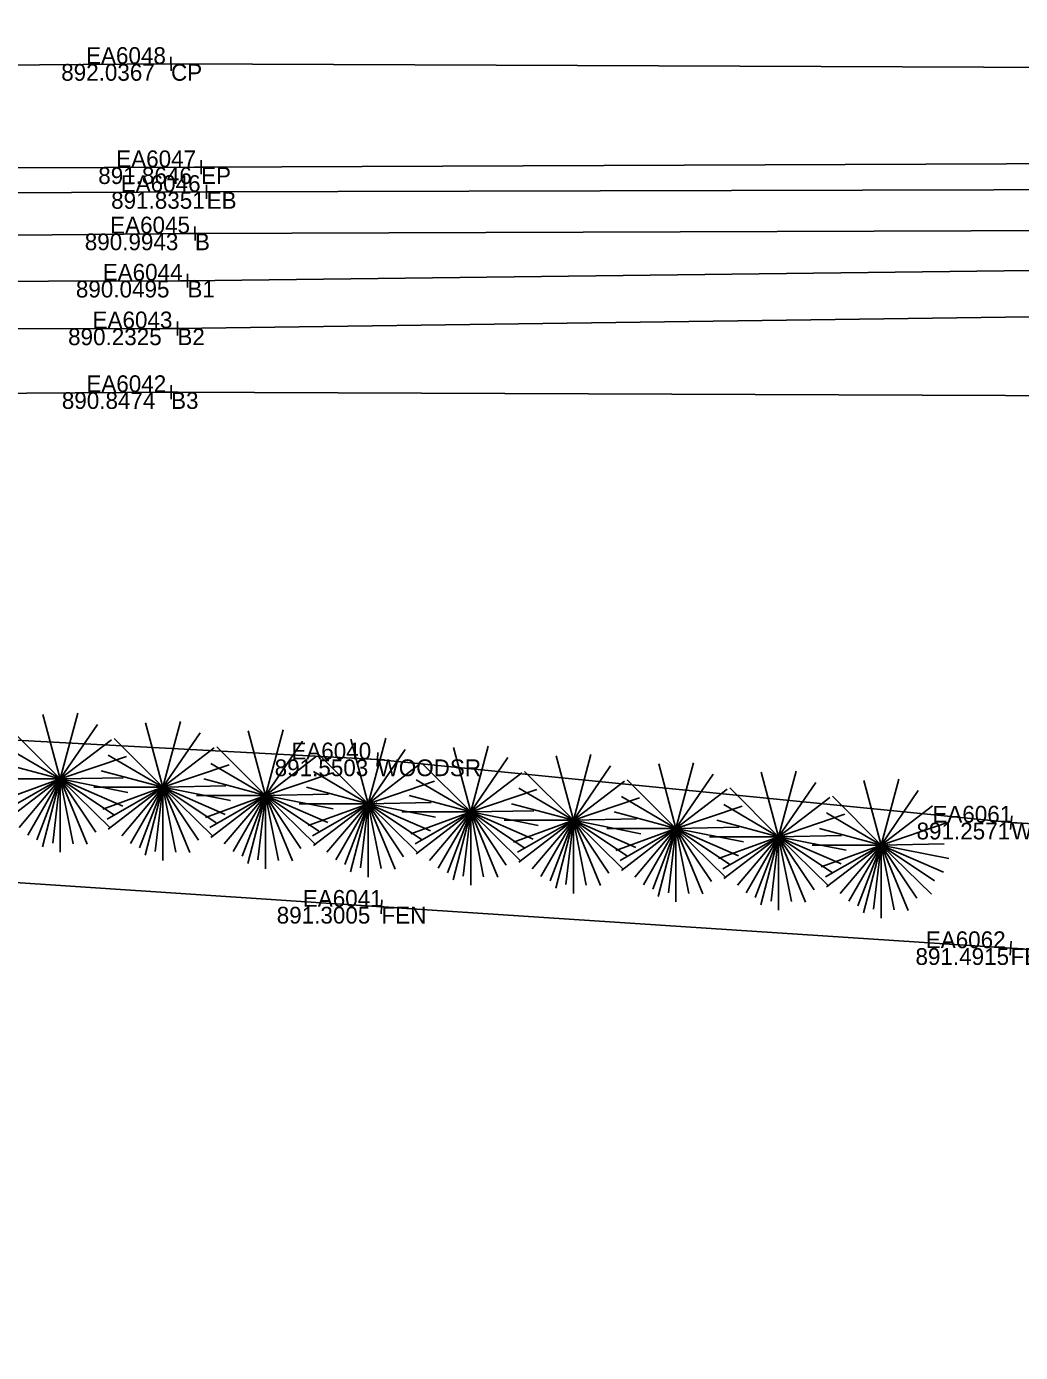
# Model space of a CAD drawing. Extents: x 179044 to 189691, y 286531 to 301257.
# Drawn here: x 179870.8 to 179941.9, y 300496.5 to 300591.3 of the extents above; entities that cross this region are included whole.
import ezdxf

# ---------------------------------------------------------------- set-up
doc = ezdxf.new("R2010")
doc.units = 0
for name, color, linetype in [('PV_X_COP', 7, 'Continuous'), ('PV_X_EOP', 7, 'Continuous'), ('PV_X_Shoulder_Aggregate', 7, 'Continuous'), ('RD_X_Fence', 7, 'Continuous'), ('SV_X_Break_Lines', 7, 'Continuous'), ('SV_X_Shot_Marker', 7, 'Continuous'), ('SV_X_Text_Comment', 7, 'Continuous'), ('SV_X_Text_Elevation', 7, 'Continuous'), ('SV_X_Text_Name', 7, 'Continuous'), ('VG_X_Cells', 7, 'Continuous'), ('VG_X_Text', 7, 'Continuous'), ('VG_X_Tree_Line_Lt', 7, 'Continuous')]:
    doc.layers.add(name, color=color, linetype=linetype)

msp = doc.modelspace()

# ---------------------------------------------------------------- linework, layer by layer
at = {"layer": 'PV_X_COP'}
msp.add_lwpolyline([(179370.611, 300584.893), (179476.831, 300585.936), (179562.951, 300586.92), (179659.852, 300587.603), (179771.173, 300587.773), (179881.154, 300588.595), (179985.728, 300588.166), (180079.826, 300588.612), (180147.691, 300589.874), (180172.034, 300590.636), (180187.456, 300591.905), (180203.618, 300593.325)], dxfattribs=at)
at = {"layer": 'PV_X_EOP'}
msp.add_lwpolyline([(179371.146, 300578.051), (179477.168, 300579.528), (179563.012, 300579.455), (179660.626, 300579.907), (179772.349, 300580.843), (179883.302, 300581.216), (179986.953, 300581.659), (180080.461, 300581.624), (180131.142, 300581.875), (180152.421, 300580.897), (180177.372, 300581.245), (180192.481, 300580.813), (180205.116, 300578.916), (180211.895, 300576.366), (180217.061, 300570.924), (180226.256, 300546.032), (180252.64, 300475.662), (180284.891, 300388.784), (180312.046, 300315.753), (180341.998, 300235.308)], dxfattribs=at)
at = {"layer": 'PV_X_Shoulder_Aggregate'}
msp.add_lwpolyline([(179563.451, 300578.229), (179660.977, 300578.016), (179772.748, 300578.901), (179883.7, 300579.446), (179986.895, 300579.719), (180080.262, 300579.655), (180131.517, 300579.632), (180152.892, 300578.404), (180177.169, 300578.87), (180192.854, 300577.824), (180203.732, 300575.396), (180212.869, 300569.272), (180224.05, 300544.426), (180250.422, 300474.503), (180282.665, 300386.992), (180309.922, 300313.986), (180339.844, 300234.334)], dxfattribs=at)
at = {"layer": 'RD_X_Fence'}
msp.add_lwpolyline([(179565.425, 300550.823), (179667.832, 300544.252), (179812.225, 300533.926), (179896.206, 300528.356), (179941.193, 300525.399), (180078.773, 300515.902), (180168.337, 300509.719), (180196.88, 300447.723), (180266.667, 300296.146), (180285.875, 300252.935)], dxfattribs=at)
at = {"layer": 'SV_X_Break_Lines'}
for points in [[(179565.115, 300573.15), (179662.025, 300574.398), (179773.068, 300575.457), (179882.867, 300576.482), (179986.954, 300576.827), (180079.906, 300577.073), (180132.276, 300575.162), (180173.558, 300573.472), (180187.352, 300573.774), (180198.853, 300570.766)], [(179565.766, 300571.109), (179663.199, 300570.888), (179773.087, 300572.831), (179882.326, 300573.106), (179987.447, 300574.391), (180079.006, 300574.101), (180132.144, 300569.99), (180164.614, 300565.351), (180185.409, 300564.026)], [(179565.763, 300567.872), (179663.335, 300568.017), (179772.883, 300569.466), (179881.609, 300569.697), (179987.857, 300571.139), (180079.155, 300570.638), (180132.418, 300565.887), (180165.824, 300561.088), (180185.221, 300560.101)], [(180320.902, 300212.184), (180282.069, 300307.438), (180254.033, 300376.286), (180214.216, 300457.225), (180192.833, 300518.475), (180187.002, 300524.649), (180178.544, 300551.918), (180167.492, 300556.189), (180133.433, 300560.27), (180078.668, 300564.705), (179988.563, 300564.714), (179881.16, 300565.14), (179774.574, 300564.41), (179665.201, 300563.792), (179565.532, 300563.693)]]:
    msp.add_lwpolyline(points, dxfattribs=at)
at = {"layer": 'SV_X_Shot_Marker'}
for p, q in [((179881.151, 300589.095), (179881.158, 300588.095)), ((179880.654, 300588.592), (179881.654, 300588.599)), ((179881.154, 300588.595), (179881.154, 300588.595)), ((179883.3, 300581.716), (179883.303, 300580.716)), ((179882.802, 300581.214), (179883.802, 300581.218)), ((179883.302, 300581.216), (179883.302, 300581.216)), ((179883.2, 300579.443), (179884.2, 300579.448)), ((179883.697, 300579.946), (179883.702, 300578.946)), ((179883.7, 300579.446), (179883.7, 300579.446)), ((179882.367, 300576.477), (179883.367, 300576.487)), ((179882.862, 300576.982), (179882.872, 300575.982)), ((179882.867, 300576.482), (179882.867, 300576.482)), ((179881.826, 300573.104), (179882.826, 300573.107)), ((179882.325, 300573.606), (179882.327, 300572.606)), ((179882.326, 300573.106), (179882.326, 300573.106)), ((179881.607, 300570.197), (179881.61, 300569.197)), ((179881.109, 300569.696), (179882.108, 300569.698)), ((179881.609, 300569.697), (179881.609, 300569.697)), ((179881.66, 300565.138), (179880.66, 300565.142)), ((179881.158, 300564.64), (179881.162, 300565.64)), ((179881.16, 300565.14), (179881.16, 300565.14)), ((179895.428, 300538.916), (179896.426, 300538.863)), ((179895.954, 300539.389), (179895.9, 300538.39)), ((179895.927, 300538.89), (179895.927, 300538.89)), ((179941.288, 300534.867), (179941.189, 300533.872)), ((179940.741, 300534.419), (179941.736, 300534.32)), ((179941.238, 300534.37), (179941.238, 300534.37)), ((179895.707, 300528.389), (179896.705, 300528.323)), ((179896.239, 300528.855), (179896.173, 300527.857)), ((179896.206, 300528.356), (179896.206, 300528.356)), ((179940.694, 300525.431), (179941.692, 300525.366)), ((179941.226, 300525.898), (179941.161, 300524.9)), ((179941.193, 300525.399), (179941.193, 300525.399))]:
    msp.add_line(p, q, dxfattribs=at)
at = {"layer": 'VG_X_Cells'}
for p, q in [((179873.234, 300537.49), (179871.999, 300542.103)), ((179873.234, 300537.49), (179874.491, 300542.188)), ((179880.573, 300536.9), (179879.338, 300541.513)), ((179880.573, 300536.9), (179881.829, 300541.598)), ((179873.234, 300537.49), (179869.744, 300540.976)), ((179873.234, 300537.49), (179875.889, 300541.375)), ((179880.573, 300536.9), (179883.228, 300540.785)), ((179887.911, 300536.31), (179886.676, 300540.923)), ((179887.911, 300536.31), (179889.167, 300541.008)), ((179873.234, 300537.49), (179869.328, 300539.786)), ((179873.234, 300537.49), (179876.891, 300540.295)), ((179880.573, 300536.9), (179877.083, 300540.386)), ((179880.573, 300536.9), (179884.229, 300539.705)), ((179887.911, 300536.31), (179884.421, 300539.796)), ((179887.911, 300536.31), (179890.566, 300540.195)), ((179895.249, 300535.72), (179894.014, 300540.333)), ((179895.249, 300535.72), (179896.506, 300540.418)), ((179895.249, 300535.72), (179897.904, 300539.605)), ((179902.587, 300535.13), (179901.352, 300539.743)), ((179902.587, 300535.13), (179903.844, 300539.828)), ((179873.234, 300537.49), (179868.821, 300538.673)), ((179873.234, 300537.49), (179877.971, 300539.096)), ((179880.573, 300536.9), (179876.666, 300539.196)), ((179887.911, 300536.31), (179884.004, 300538.606)), ((179887.911, 300536.31), (179891.567, 300539.115)), ((179895.249, 300535.72), (179891.759, 300539.206)), ((179902.587, 300535.13), (179899.097, 300538.616)), ((179902.587, 300535.13), (179905.242, 300539.015)), ((179909.925, 300534.54), (179908.69, 300539.153)), ((179909.925, 300534.54), (179911.182, 300539.238)), ((179917.264, 300533.95), (179918.52, 300538.648)), ((179880.573, 300536.9), (179876.159, 300538.083)), ((179880.573, 300536.9), (179885.309, 300538.506)), ((179887.911, 300536.31), (179892.647, 300537.916)), ((179895.249, 300535.72), (179891.342, 300538.016)), ((179895.249, 300535.72), (179898.906, 300538.525)), ((179902.587, 300535.13), (179906.244, 300537.935)), ((179909.925, 300534.54), (179906.435, 300538.026)), ((179909.925, 300534.54), (179912.58, 300538.425)), ((179917.264, 300533.95), (179916.029, 300538.563)), ((179917.264, 300533.95), (179919.919, 300537.835)), ((179924.602, 300533.36), (179923.367, 300537.973)), ((179924.602, 300533.36), (179925.859, 300538.058)), ((179868.299, 300537.49), (179873.234, 300537.49)), ((179873.234, 300537.49), (179868.944, 300535.928)), ((179873.234, 300537.49), (179869.251, 300535.208)), ((179873.234, 300537.49), (179869.328, 300534.495)), ((179873.234, 300537.49), (179870.289, 300534.023)), ((179873.234, 300537.49), (179870.916, 300533.475)), ((179873.234, 300537.49), (179871.569, 300533.15)), ((179873.234, 300537.49), (179871.971, 300532.633)), ((179873.234, 300537.49), (179872.693, 300532.898)), ((179873.234, 300537.49), (179877.744, 300537.581)), ((179873.234, 300532.25), (179873.234, 300537.49)), ((179873.234, 300537.49), (179874.156, 300532.853)), ((179873.234, 300537.49), (179875.168, 300532.821)), ((179873.234, 300537.49), (179875.771, 300533.696)), ((179873.234, 300537.49), (179876.823, 300533.968)), ((179873.234, 300537.49), (179877.056, 300534.935)), ((179873.234, 300537.49), (179877.699, 300535.548)), ((179873.234, 300537.49), (179878.063, 300536.531)), ((179875.638, 300536.9), (179880.573, 300536.9)), ((179880.573, 300536.9), (179876.283, 300535.338)), ((179880.573, 300536.9), (179876.589, 300534.618)), ((179880.573, 300536.9), (179876.666, 300533.905)), ((179880.573, 300536.9), (179877.628, 300533.433)), ((179880.573, 300536.9), (179878.254, 300532.885)), ((179880.573, 300536.9), (179878.908, 300532.56)), ((179880.573, 300536.9), (179879.309, 300532.043)), ((179880.573, 300536.9), (179880.031, 300532.308)), ((179880.573, 300536.9), (179885.083, 300536.991)), ((179880.573, 300531.66), (179880.573, 300536.9)), ((179880.573, 300536.9), (179881.494, 300532.263)), ((179880.573, 300536.9), (179882.506, 300532.231)), ((179880.573, 300536.9), (179883.109, 300533.106)), ((179880.573, 300536.9), (179884.161, 300533.378)), ((179880.573, 300536.9), (179884.394, 300534.345)), ((179880.573, 300536.9), (179885.038, 300534.958)), ((179880.573, 300536.9), (179885.401, 300535.941)), ((179887.911, 300536.31), (179883.497, 300537.493)), ((179895.249, 300535.72), (179890.836, 300536.903)), ((179895.249, 300535.72), (179899.986, 300537.326)), ((179902.587, 300535.13), (179898.681, 300537.426)), ((179902.587, 300535.13), (179907.324, 300536.736)), ((179909.925, 300534.54), (179906.019, 300536.836)), ((179909.925, 300534.54), (179913.582, 300537.345)), ((179917.264, 300533.95), (179913.774, 300537.436)), ((179917.264, 300533.95), (179920.92, 300536.755)), ((179924.602, 300533.36), (179921.112, 300536.846)), ((179924.602, 300533.36), (179927.257, 300537.245)), ((179931.94, 300532.77), (179930.705, 300537.383)), ((179931.94, 300532.77), (179933.197, 300537.468)), ((179882.976, 300536.31), (179887.911, 300536.31)), ((179887.911, 300536.31), (179883.621, 300534.748)), ((179887.911, 300536.31), (179883.927, 300534.028)), ((179887.911, 300536.31), (179884.004, 300533.315)), ((179887.911, 300536.31), (179884.966, 300532.843)), ((179887.911, 300536.31), (179885.592, 300532.295)), ((179887.911, 300536.31), (179886.246, 300531.97)), ((179887.911, 300536.31), (179886.647, 300531.453)), ((179887.911, 300536.31), (179887.369, 300531.718)), ((179887.911, 300536.31), (179892.421, 300536.401)), ((179887.911, 300531.07), (179887.911, 300536.31)), ((179887.911, 300536.31), (179888.832, 300531.673)), ((179887.911, 300536.31), (179889.844, 300531.641)), ((179887.911, 300536.31), (179890.447, 300532.516)), ((179887.911, 300536.31), (179891.499, 300532.788)), ((179887.911, 300536.31), (179891.732, 300533.755)), ((179887.911, 300536.31), (179892.376, 300534.368)), ((179887.911, 300536.31), (179892.739, 300535.351)), ((179895.249, 300535.72), (179899.759, 300535.811)), ((179902.587, 300535.13), (179898.174, 300536.313)), ((179909.925, 300534.54), (179914.662, 300536.146)), ((179917.264, 300533.95), (179913.357, 300536.246)), ((179924.602, 300533.36), (179928.259, 300536.165)), ((179931.94, 300532.77), (179928.45, 300536.256)), ((179931.94, 300532.77), (179934.595, 300536.655)), ((179890.314, 300535.72), (179895.249, 300535.72)), ((179895.249, 300535.72), (179890.959, 300534.158)), ((179895.249, 300535.72), (179891.266, 300533.438)), ((179895.249, 300535.72), (179891.342, 300532.725)), ((179895.249, 300535.72), (179892.304, 300532.253)), ((179895.249, 300535.72), (179892.931, 300531.705)), ((179895.249, 300535.72), (179893.584, 300531.38)), ((179895.249, 300535.72), (179893.986, 300530.863)), ((179895.249, 300535.72), (179894.707, 300531.128)), ((179895.249, 300530.48), (179895.249, 300535.72)), ((179895.249, 300535.72), (179896.171, 300531.083)), ((179895.249, 300535.72), (179897.182, 300531.051)), ((179895.249, 300535.72), (179897.786, 300531.926)), ((179895.249, 300535.72), (179898.837, 300532.198)), ((179895.249, 300535.72), (179899.071, 300533.165)), ((179895.249, 300535.72), (179899.714, 300533.778)), ((179895.249, 300535.72), (179900.077, 300534.761)), ((179897.652, 300535.13), (179902.587, 300535.13)), ((179902.587, 300535.13), (179898.297, 300533.568)), ((179902.587, 300535.13), (179898.604, 300532.848)), ((179902.587, 300535.13), (179898.681, 300532.135)), ((179902.587, 300535.13), (179899.642, 300531.663)), ((179902.587, 300535.13), (179900.269, 300531.115)), ((179902.587, 300535.13), (179900.922, 300530.79)), ((179902.587, 300535.13), (179901.324, 300530.273)), ((179902.587, 300535.13), (179902.046, 300530.538)), ((179902.587, 300535.13), (179907.097, 300535.221)), ((179902.587, 300529.89), (179902.587, 300535.13)), ((179902.587, 300535.13), (179903.509, 300530.493)), ((179902.587, 300535.13), (179904.521, 300530.461)), ((179902.587, 300535.13), (179905.124, 300531.336)), ((179902.587, 300535.13), (179906.176, 300531.608)), ((179902.587, 300535.13), (179906.409, 300532.575)), ((179902.587, 300535.13), (179907.052, 300533.188)), ((179902.587, 300535.13), (179907.416, 300534.171)), ((179909.925, 300534.54), (179905.512, 300535.723)), ((179917.264, 300533.95), (179912.85, 300535.133)), ((179917.264, 300533.95), (179922, 300535.556)), ((179924.602, 300533.36), (179920.695, 300535.656)), ((179924.602, 300533.36), (179929.339, 300534.966)), ((179931.94, 300532.77), (179928.034, 300535.066)), ((179931.94, 300532.77), (179935.597, 300535.575)), ((179904.99, 300534.54), (179909.925, 300534.54)), ((179909.925, 300534.54), (179905.635, 300532.978)), ((179909.925, 300534.54), (179905.942, 300532.258)), ((179909.925, 300534.54), (179906.019, 300531.545)), ((179909.925, 300534.54), (179906.98, 300531.073)), ((179909.925, 300534.54), (179907.607, 300530.525)), ((179909.925, 300534.54), (179908.26, 300530.2)), ((179909.925, 300534.54), (179908.662, 300529.683)), ((179909.925, 300534.54), (179909.384, 300529.948)), ((179909.925, 300534.54), (179914.435, 300534.631)), ((179909.925, 300529.3), (179909.925, 300534.54)), ((179909.925, 300534.54), (179910.847, 300529.903)), ((179909.925, 300534.54), (179911.859, 300529.871)), ((179909.925, 300534.54), (179912.462, 300530.746)), ((179909.925, 300534.54), (179913.514, 300531.018)), ((179909.925, 300534.54), (179913.747, 300531.985)), ((179909.925, 300534.54), (179914.39, 300532.598)), ((179909.925, 300534.54), (179914.754, 300533.581)), ((179912.329, 300533.95), (179917.264, 300533.95)), ((179917.264, 300533.95), (179912.974, 300532.388)), ((179917.264, 300533.95), (179913.28, 300531.668)), ((179917.264, 300533.95), (179913.357, 300530.955)), ((179917.264, 300533.95), (179914.319, 300530.483)), ((179917.264, 300533.95), (179914.945, 300529.935)), ((179917.264, 300533.95), (179915.599, 300529.61)), ((179917.264, 300533.95), (179916, 300529.093)), ((179917.264, 300533.95), (179916.722, 300529.358)), ((179917.264, 300533.95), (179921.774, 300534.041)), ((179917.264, 300528.71), (179917.264, 300533.95)), ((179917.264, 300533.95), (179918.185, 300529.313)), ((179917.264, 300533.95), (179919.197, 300529.281)), ((179917.264, 300533.95), (179919.8, 300530.156)), ((179917.264, 300533.95), (179920.852, 300530.428)), ((179917.264, 300533.95), (179921.085, 300531.395)), ((179917.264, 300533.95), (179921.729, 300532.008)), ((179917.264, 300533.95), (179922.092, 300532.991)), ((179924.602, 300533.36), (179920.189, 300534.543)), ((179931.94, 300532.77), (179927.527, 300533.953)), ((179931.94, 300532.77), (179936.677, 300534.376)), ((179919.667, 300533.36), (179924.602, 300533.36)), ((179924.602, 300533.36), (179920.312, 300531.798)), ((179924.602, 300533.36), (179920.619, 300531.078)), ((179924.602, 300533.36), (179920.695, 300530.365)), ((179924.602, 300533.36), (179921.657, 300529.893)), ((179924.602, 300533.36), (179922.284, 300529.345)), ((179924.602, 300533.36), (179922.937, 300529.02)), ((179924.602, 300533.36), (179923.339, 300528.503)), ((179924.602, 300533.36), (179924.06, 300528.768)), ((179924.602, 300533.36), (179929.112, 300533.451)), ((179924.602, 300528.12), (179924.602, 300533.36)), ((179924.602, 300533.36), (179925.524, 300528.723)), ((179924.602, 300533.36), (179926.535, 300528.691)), ((179924.602, 300533.36), (179927.139, 300529.566)), ((179924.602, 300533.36), (179928.19, 300529.838)), ((179924.602, 300533.36), (179928.424, 300530.805)), ((179924.602, 300533.36), (179929.067, 300531.418)), ((179924.602, 300533.36), (179929.43, 300532.401)), ((179927.005, 300532.77), (179931.94, 300532.77)), ((179931.94, 300532.77), (179927.65, 300531.208)), ((179931.94, 300532.77), (179927.957, 300530.488)), ((179931.94, 300532.77), (179928.034, 300529.775)), ((179931.94, 300532.77), (179928.995, 300529.303)), ((179931.94, 300532.77), (179929.622, 300528.755)), ((179931.94, 300532.77), (179930.275, 300528.43)), ((179931.94, 300532.77), (179930.677, 300527.913)), ((179931.94, 300532.77), (179931.399, 300528.178)), ((179931.94, 300532.77), (179936.45, 300532.861)), ((179931.94, 300527.53), (179931.94, 300532.77)), ((179931.94, 300532.77), (179932.862, 300528.133)), ((179931.94, 300532.77), (179933.874, 300528.101)), ((179931.94, 300532.77), (179934.477, 300528.976)), ((179931.94, 300532.77), (179935.529, 300529.248)), ((179931.94, 300532.77), (179935.762, 300530.215)), ((179931.94, 300532.77), (179936.405, 300530.828)), ((179931.94, 300532.77), (179936.769, 300531.811))]:
    msp.add_line(p, q, dxfattribs=at)
at = {"layer": 'VG_X_Tree_Line_Lt'}
msp.add_lwpolyline([(179569.069, 300551.827), (179569.572, 300561.616), (179669.01, 300553.205), (179812.545, 300543.336), (179895.927, 300538.89), (179941.238, 300534.37), (180108.398, 300524.388), (180109.229, 300515.004)], dxfattribs=at)

# ---------------------------------------------------------------- texts
at = {"layer": 'SV_X_Text_Comment'}
for s, height, p in [('CP', 1.2, (179881.154, 300587.395)), ('EP', 1.2, (179883.302, 300580.016)), ('EB', 1.2, (179883.7, 300578.246)), ('B', 1.2, (179882.867, 300575.282)), ('B1', 1.2, (179882.326, 300571.906)), ('B2', 1.2, (179881.609, 300568.497)), ('B3', 1.2, (179881.16, 300563.94)), ('WOODSR', 1.2, (179895.927, 300537.69)), ('TE', 0.12, (179873.234, 300537.37)), ('TE', 0.12, (179880.573, 300536.78)), ('TE', 0.12, (179887.911, 300536.19)), ('TE', 0.12, (179895.249, 300535.6)), ('TE', 0.12, (179902.587, 300535.01)), ('TE', 0.12, (179909.925, 300534.42)), ('TE', 0.12, (179917.264, 300533.83)), ('WOODSR', 1.2, (179941.238, 300533.17)), ('TE', 0.12, (179924.602, 300533.24)), ('TE', 0.12, (179931.94, 300532.65)), ('FEN', 1.2, (179896.206, 300527.156)), ('FEN', 1.2, (179941.193, 300524.199))]:
    msp.add_text(s, height=height, dxfattribs=at).set_placement(p)
at = {"layer": 'SV_X_Text_Elevation'}
for s, p in [('892.0367', (179873.303, 300587.395)), ('891.8646', (179875.952, 300580.016)), ('891.8351', (179876.872, 300578.246)), ('890.9943', (179874.987, 300575.282)), ('890.0495', (179874.352, 300571.906)), ('890.2325', (179873.795, 300568.497)), ('890.8474', (179873.346, 300563.94)), ('891.5503', (179888.567, 300537.69)), ('891.2571', (179934.467, 300533.17)), ('891.3005', (179888.714, 300527.156)), ('891.4915', (179934.392, 300524.199))]:
    msp.add_text(s, height=1.2, dxfattribs=at).set_placement(p)
at = {"layer": 'SV_X_Text_Name'}
for s, p in [('EA6048', (179875.079, 300588.595)), ('EA6047', (179877.236, 300581.216)), ('EA6046', (179877.559, 300579.446)), ('EA6045', (179876.802, 300576.482)), ('EA6044', (179876.27, 300573.106)), ('EA6043', (179875.543, 300569.697)), ('EA6042', (179875.103, 300565.14)), ('EA6040', (179889.758, 300538.89)), ('EA6061', (179935.601, 300534.37)), ('EA6041', (179890.578, 300528.356)), ('EA6062', (179935.128, 300525.399))]:
    msp.add_text(s, height=1.2, dxfattribs=at).set_placement(p)
at = {"layer": 'VG_X_Text'}
for p in [(179873.234, 300537.49), (179880.573, 300536.9), (179887.911, 300536.31), (179895.249, 300535.72), (179902.587, 300535.13), (179909.925, 300534.54), (179917.264, 300533.95), (179924.602, 300533.36), (179931.94, 300532.77)]:
    msp.add_text(' NOTE:8', height=0.12, dxfattribs=at).set_placement(p)

doc.saveas('drawing.dxf')
